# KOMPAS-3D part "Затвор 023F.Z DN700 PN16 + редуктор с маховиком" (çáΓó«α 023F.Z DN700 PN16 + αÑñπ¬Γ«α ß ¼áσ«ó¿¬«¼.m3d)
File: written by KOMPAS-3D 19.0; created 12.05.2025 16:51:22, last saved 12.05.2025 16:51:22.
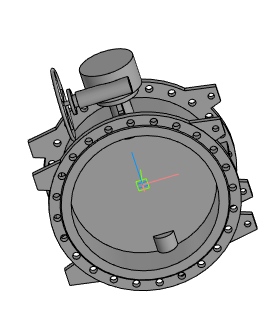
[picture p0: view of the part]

Document properties: Полное имя файла: Затвор 023F.Z DN700 PN16 + редуктор с маховиком.a3d

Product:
- Part/product: Затвор 023F.Z DN700 PN16 + редуктор с маховиком
    Масса: 596.964

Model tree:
1. Операция без истории:1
